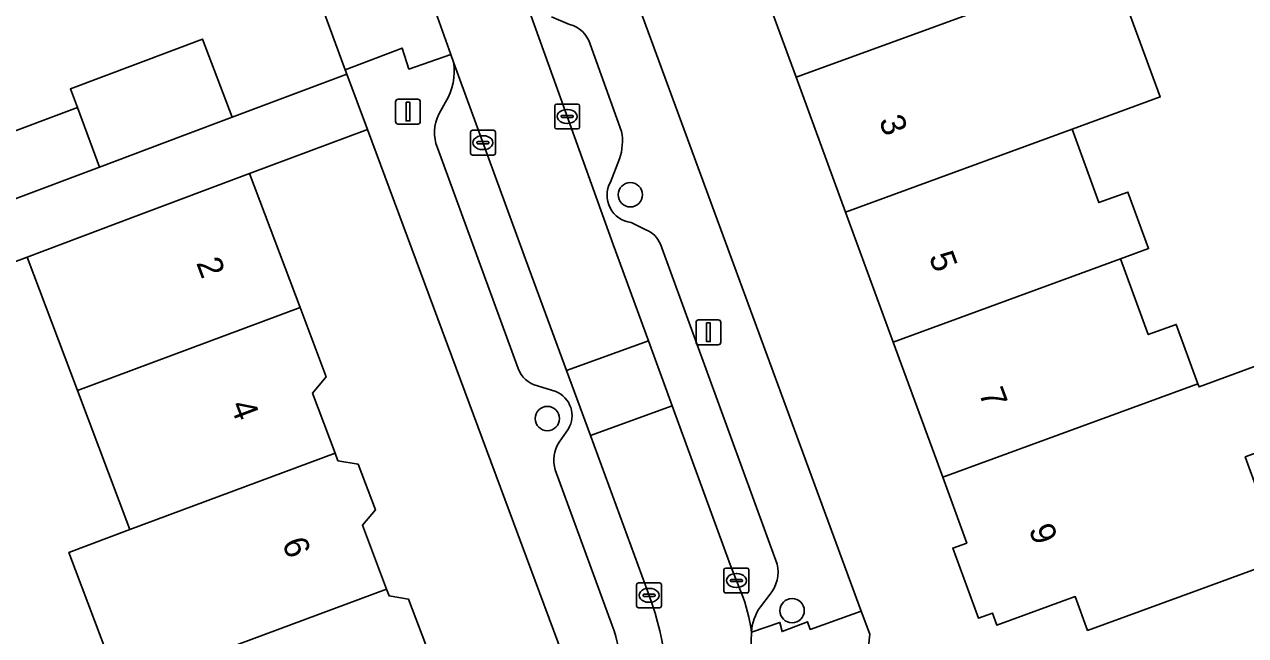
# Model space of a CAD drawing. Extents: x 161258 to 161838, y 380833 to 381727.
# Drawn here: x 161688.41 to 161737.48, y 381440.54 to 381465.11 of the extents above; entities that cross this region are included whole.
import ezdxf

# ---------------------------------------------------------------- set-up
doc = ezdxf.new("R2010")
doc.units = 0
for name, color, linetype in [('IMGEO_Boom', 7, 'Continuous'), ('IMGEO_Erf', 7, 'Continuous'), ('IMGEO_Kolk', 7, 'Continuous'), ('IMGEO_Lichtmast', 7, 'Continuous'), ('IMGEO_Pand', 7, 'Continuous'), ('IMGEO_Pand_nummerreeks', 7, 'Continuous'), ('IMGEO_Parkeervlak_open', 7, 'Continuous'), ('IMGEO_Rijbaan_lokaal_open', 7, 'Continuous'), ('IMGEO_Voetpad_open', 7, 'Continuous')]:
    doc.layers.add(name, color=color, linetype=linetype)

msp = doc.modelspace()

# ---------------------------------------------------------------- linework, layer by layer
at = {"layer": 'IMGEO_Boom'}
for centre in [(161712.757, 381458.263), (161709.426, 381449.266), (161719.258, 381441.543)]:
    msp.add_circle(centre, 0.489, dxfattribs=at)
at = {"layer": 'IMGEO_Erf'}
for points in [[(161650.576, 381442.391), (161665.897, 381448.031), (161665.866, 381448.114), (161663.067, 381447.101), (161662.84, 381447.729), (161661.976, 381450.118), (161664.775, 381451.131), (161665.341, 381449.566), (161680.052, 381455.096), (161679.094, 381457.641), (161682.243, 381458.826), (161683.201, 381456.28), (161687.935, 381458.06), (161687.033, 381460.457), (161690.542, 381461.777), (161690.266, 381462.521), (161695.576, 381464.518), (161696.757, 381461.377), (161701.371, 381463.111), (161701.306, 381463.287), (161700.279, 381466.054), (161692.567, 381486.83), (161622.485, 381460.994)], [(161738.57, 381470.014), (161737.144, 381473.959), (161735.098, 381474.813), (161727.787, 381472.135), (161728.72, 381469.59), (161729.505, 381469.878), (161730.54, 381467.051), (161732.063, 381467.606), (161734.046, 381462.193), (161733.027, 381461.82), (161730.506, 381460.896), (161731.586, 381457.948), (161732.749, 381458.374), (161733.581, 381456.102), (161732.452, 381455.688), (161733.568, 381452.64), (161734.69, 381453.051), (161735.563, 381450.667), (161735.609, 381450.542), (161739.215, 381451.864)], [(161740.346, 381448.778), (161737.465, 381447.722), (161738.967, 381443.62), (161735.595, 381442.384), (161731.131, 381440.748), (161730.632, 381442.111), (161727.489, 381440.959), (161727.31, 381441.447), (161726.747, 381441.241), (161725.715, 381444.058), (161726.278, 381444.264), (161725.309, 381446.909), (161723.319, 381452.34), (161721.406, 381457.561), (161719.415, 381462.994), (161717.453, 381468.348), (161712.809, 381466.642), (161722.039, 381441.525), (161722.379, 381440.599), (161722.102, 381438)], [(161710.363, 381438.89), (161702.199, 381460.88), (161697.459, 381459.12), (161699.487, 381453.726), (161700.532, 381450.947), (161699.991, 381450.289), (161700.897, 381447.88), (161701.013, 381447.57), (161701.823, 381447.436), (161702.514, 381445.6), (161702, 381444.975), (161702.963, 381442.413), (161703.066, 381442.139), (161703.843, 381442.011), (161704.537, 381440.165)], [(161692.261, 381438.418), (161690.203, 381443.888), (161692.652, 381444.802), (161690.549, 381450.391), (161688.53, 381455.758), (161668.011, 381448.039), (161671.253, 381439.144)]]:
    msp.add_lwpolyline(points, dxfattribs=at)
at = {"layer": 'IMGEO_Kolk'}
for p, q in [((161709.721, 381460.985), (161709.721, 381461.837)), ((161709.796, 381461.911), (161710.648, 381461.911)), ((161710.209, 381461.691), (161710.234, 381461.691)), ((161710.722, 381461.837), (161710.722, 381460.985)), ((161709.98, 381461.405), (161709.98, 381461.417)), ((161710.418, 381461.368), (161710.02, 381461.368)), ((161710.023, 381461.454), (161710.421, 381461.454)), ((161710.232, 381461.131), (161710.207, 381461.131)), ((161710.464, 381461.417), (161710.464, 381461.405)), ((161706.337, 381459.931), (161706.337, 381460.783)), ((161706.412, 381460.857), (161707.264, 381460.857)), ((161706.825, 381460.637), (161706.85, 381460.637)), ((161707.338, 381460.783), (161707.338, 381459.931)), ((161710.648, 381460.911), (161709.796, 381460.911)), ((161706.596, 381460.351), (161706.596, 381460.363)), ((161707.034, 381460.314), (161706.636, 381460.314)), ((161706.639, 381460.4), (161707.037, 381460.4)), ((161707.08, 381460.363), (161707.08, 381460.351)), ((161707.264, 381459.857), (161706.412, 381459.857)), ((161706.848, 381460.077), (161706.823, 381460.077)), ((161716.519, 381442.329), (161716.519, 381443.181)), ((161716.594, 381443.255), (161717.446, 381443.255)), ((161717.007, 381443.035), (161717.032, 381443.035)), ((161717.52, 381443.181), (161717.52, 381442.329)), ((161713.011, 381441.735), (161713.011, 381442.587)), ((161713.086, 381442.661), (161713.938, 381442.661)), ((161714.012, 381442.587), (161714.012, 381441.735)), ((161716.778, 381442.749), (161716.778, 381442.761)), ((161717.216, 381442.712), (161716.818, 381442.712)), ((161716.821, 381442.798), (161717.219, 381442.798)), ((161717.03, 381442.475), (161717.005, 381442.475)), ((161717.262, 381442.761), (161717.262, 381442.749)), ((161713.27, 381442.155), (161713.27, 381442.167)), ((161713.708, 381442.118), (161713.31, 381442.118)), ((161713.313, 381442.204), (161713.711, 381442.204)), ((161713.499, 381442.441), (161713.524, 381442.441)), ((161713.754, 381442.167), (161713.754, 381442.155)), ((161717.446, 381442.255), (161716.594, 381442.255)), ((161713.938, 381441.661), (161713.086, 381441.661)), ((161713.522, 381441.881), (161713.497, 381441.881))]:
    msp.add_line(p, q, dxfattribs=at)
for points in [[(161709.721, 381460.985), (161709.721, 381461.837)], [(161709.796, 381461.911), (161710.648, 381461.911)], [(161710.722, 381461.837), (161710.722, 381460.985)], [(161706.337, 381459.931), (161706.337, 381460.783)], [(161706.412, 381460.857), (161707.264, 381460.857)], [(161707.338, 381460.783), (161707.338, 381459.931)], [(161710.648, 381460.911), (161709.796, 381460.911)], [(161707.264, 381459.857), (161706.412, 381459.857)], [(161716.519, 381442.329), (161716.519, 381443.181)], [(161716.594, 381443.255), (161717.446, 381443.255)], [(161717.52, 381443.181), (161717.52, 381442.329)], [(161713.011, 381441.735), (161713.011, 381442.587)], [(161713.086, 381442.661), (161713.938, 381442.661)], [(161714.012, 381442.587), (161714.012, 381441.735)], [(161717.446, 381442.255), (161716.594, 381442.255)], [(161713.938, 381441.661), (161713.086, 381441.661)]]:
    msp.add_lwpolyline(points, dxfattribs=at)
for centre, radius, start, end in [((161709.798, 381461.835), 0.0765, 91.552, 178.448), ((161709.798, 381461.835), 0.0765, 91.552, 178.448), ((161710.646, 381461.835), 0.0765, 1.552, 88.448), ((161710.646, 381461.835), 0.0765, 1.552, 88.448), ((161710.02, 381461.414), 0.0403, 85.8775, 175.7526), ((161710.017, 381461.404), 0.0366, 178.938, 274.7102), ((161710.421, 381461.411), 0.043, 264.8664, 352.4533), ((161710.425, 381461.416), 0.0386, 1.7309, 96.639), ((161706.414, 381460.781), 0.0765, 91.552, 178.448), ((161706.414, 381460.781), 0.0765, 91.552, 178.448), ((161707.262, 381460.781), 0.0765, 1.552, 88.448), ((161707.262, 381460.781), 0.0765, 1.552, 88.448), ((161709.798, 381460.987), 0.0765, 181.552, 268.448), ((161709.798, 381460.987), 0.0765, 181.552, 268.448), ((161710.646, 381460.987), 0.0765, 271.552, 358.448), ((161710.646, 381460.987), 0.0765, 271.552, 358.448), ((161706.636, 381460.36), 0.0403, 85.8775, 175.7526), ((161706.633, 381460.35), 0.0366, 178.938, 274.7102), ((161707.037, 381460.357), 0.043, 264.8664, 352.4533), ((161707.041, 381460.362), 0.0386, 1.7309, 96.639), ((161706.414, 381459.933), 0.0765, 181.552, 268.448), ((161706.414, 381459.933), 0.0765, 181.552, 268.448), ((161707.262, 381459.933), 0.0765, 271.552, 358.448), ((161707.262, 381459.933), 0.0765, 271.552, 358.448), ((161716.596, 381443.179), 0.0765, 91.552, 178.448), ((161716.596, 381443.179), 0.0765, 91.552, 178.448), ((161717.444, 381443.179), 0.0765, 1.552, 88.448), ((161717.444, 381443.179), 0.0765, 1.552, 88.448), ((161713.088, 381442.585), 0.0765, 91.552, 178.448), ((161713.088, 381442.585), 0.0765, 91.552, 178.448), ((161713.936, 381442.585), 0.0765, 1.552, 88.448), ((161713.936, 381442.585), 0.0765, 1.552, 88.448), ((161716.818, 381442.758), 0.0403, 85.8775, 175.7526), ((161716.815, 381442.748), 0.0366, 178.938, 274.7102), ((161717.219, 381442.755), 0.043, 264.8664, 352.4533), ((161717.223, 381442.76), 0.0386, 1.7309, 96.639), ((161713.31, 381442.164), 0.0403, 85.8775, 175.7526), ((161713.307, 381442.154), 0.0366, 178.938, 274.7102), ((161713.711, 381442.161), 0.043, 264.8664, 352.4533), ((161713.715, 381442.166), 0.0386, 1.7309, 96.639), ((161716.596, 381442.331), 0.0765, 181.552, 268.448), ((161716.596, 381442.331), 0.0765, 181.552, 268.448), ((161717.444, 381442.331), 0.0765, 271.552, 358.448), ((161717.444, 381442.331), 0.0765, 271.552, 358.448), ((161713.088, 381441.737), 0.0765, 181.552, 268.448), ((161713.088, 381441.737), 0.0765, 181.552, 268.448), ((161713.936, 381441.737), 0.0765, 271.552, 358.448), ((161713.936, 381441.737), 0.0765, 271.552, 358.448)]:
    msp.add_arc(centre, radius, start, end, dxfattribs=at)
for centre, major_axis, ratio, start_param, end_param in [((161710.208, 381461.411), (-0.387, 0.002), 0.722429, 4.712389, 7.853982), ((161710.233, 381461.411), (-0.39, 0.002), 0.717154, 1.570796, 4.712389), ((161706.824, 381460.357), (-0.387, 0.002), 0.722429, 4.712389, 7.853982), ((161706.849, 381460.357), (-0.39, 0.002), 0.717154, 1.570796, 4.712389), ((161717.006, 381442.755), (-0.387, 0.002), 0.722429, 4.712389, 7.853982), ((161717.031, 381442.755), (-0.39, 0.002), 0.717154, 1.570796, 4.712389), ((161713.498, 381442.161), (-0.387, 0.002), 0.722429, 4.712389, 7.853982), ((161713.523, 381442.161), (-0.39, 0.002), 0.717154, 1.570796, 4.712389)]:
    msp.add_ellipse(centre, major_axis=major_axis, ratio=ratio, start_param=start_param, end_param=end_param, dxfattribs=at)
at = {"layer": 'IMGEO_Lichtmast'}
for p, q in [((161703.43, 381462.105), (161704.22, 381462.105)), ((161704.22, 381462.105), (161703.43, 381462.105)), ((161703.33, 381461.205), (161703.33, 381462.005)), ((161703.33, 381462.005), (161703.33, 381461.205)), ((161704.32, 381462.005), (161704.32, 381461.205)), ((161704.32, 381461.205), (161704.32, 381462.005)), ((161704.22, 381461.105), (161703.43, 381461.105)), ((161703.43, 381461.105), (161704.22, 381461.105)), ((161715.402, 381452.334), (161715.402, 381453.134)), ((161715.402, 381453.134), (161715.402, 381452.334)), ((161715.502, 381453.234), (161716.292, 381453.234)), ((161716.292, 381453.234), (161715.502, 381453.234)), ((161716.392, 381453.134), (161716.392, 381452.334)), ((161716.392, 381452.334), (161716.392, 381453.134)), ((161716.292, 381452.234), (161715.502, 381452.234)), ((161715.502, 381452.234), (161716.292, 381452.234))]:
    msp.add_line(p, q, dxfattribs=at)
for points in [[(161703.75, 381461.98), (161703.9, 381461.98), (161703.9, 381461.23), (161703.75, 381461.23), (161703.75, 381461.98)], [(161715.822, 381453.109), (161715.972, 381453.109), (161715.972, 381452.359), (161715.822, 381452.359), (161715.822, 381453.109)]]:
    msp.add_lwpolyline(points, dxfattribs=at)
for centre, start, end in [((161703.43, 381462.005), 90, 180), ((161703.43, 381462.005), 90, 180), ((161704.22, 381462.005), 0, 90), ((161704.22, 381462.005), 360, 90), ((161703.43, 381461.205), 180, 270), ((161703.43, 381461.205), 180, 270), ((161704.22, 381461.205), 270, 0), ((161704.22, 381461.205), 270, 0), ((161715.502, 381453.134), 90, 180), ((161715.502, 381453.134), 90, 180), ((161716.292, 381453.134), 0, 90), ((161716.292, 381453.134), 360, 90), ((161715.502, 381452.334), 180, 270), ((161715.502, 381452.334), 180, 270), ((161716.292, 381452.334), 270, 0), ((161716.292, 381452.334), 270, 0)]:
    msp.add_arc(centre, 0.1, start, end, dxfattribs=at)
at = {"layer": 'IMGEO_Pand'}
for points in [[(161728.72, 381469.59), (161727.787, 381472.135), (161722.096, 381470.05), (161717.453, 381468.348), (161719.415, 381462.994), (161730.54, 381467.051), (161729.505, 381469.878)], [(161730.54, 381467.051), (161719.415, 381462.994), (161721.406, 381457.561), (161730.506, 381460.896), (161733.027, 381461.82), (161734.046, 381462.193), (161732.063, 381467.606)], [(161690.266, 381462.521), (161690.542, 381461.777), (161691.433, 381459.375), (161694.766, 381460.628), (161696.757, 381461.377), (161695.576, 381464.518)], [(161691.433, 381459.375), (161690.542, 381461.777), (161687.033, 381460.457), (161687.935, 381458.06)], [(161732.749, 381458.374), (161731.586, 381457.948), (161730.506, 381460.896), (161721.406, 381457.561), (161723.319, 381452.34), (161732.452, 381455.688), (161733.581, 381456.102)], [(161690.549, 381450.391), (161699.487, 381453.726), (161697.459, 381459.12), (161692.779, 381457.36), (161688.53, 381455.758)], [(161734.69, 381453.051), (161733.568, 381452.64), (161732.452, 381455.688), (161723.319, 381452.34), (161725.309, 381446.909), (161735.563, 381450.667)], [(161700.897, 381447.88), (161699.991, 381450.289), (161700.532, 381450.947), (161699.487, 381453.726), (161690.549, 381450.391), (161692.652, 381444.802)], [(161735.563, 381450.667), (161725.309, 381446.909), (161726.278, 381444.264), (161725.715, 381444.058), (161726.747, 381441.241), (161727.31, 381441.447), (161727.489, 381440.959), (161730.632, 381442.111), (161731.131, 381440.748), (161735.595, 381442.384), (161738.967, 381443.62), (161737.465, 381447.722), (161740.346, 381448.778), (161739.215, 381451.864), (161735.609, 381450.542)], [(161702, 381444.975), (161702.514, 381445.6), (161701.823, 381447.436), (161701.013, 381447.57), (161700.897, 381447.88), (161692.652, 381444.802), (161690.203, 381443.888), (161692.261, 381438.418), (161693.067, 381438.719), (161693.35, 381438.825), (161693.713, 381438.96), (161702.963, 381442.413)], [(161703.945, 381433.024), (161703.968, 381433.23), (161704.731, 381433.565), (161704.948, 381435.524), (161704.273, 381436.021), (161704.518, 381438.234), (161704.027, 381439.544), (161704.537, 381440.165), (161703.843, 381442.011), (161703.066, 381442.139), (161702.963, 381442.413), (161693.713, 381438.96), (161694.64, 381436.494), (161694.374, 381434.1)]]:
    msp.add_lwpolyline(points, close=True, dxfattribs=at)
at = {"layer": 'IMGEO_Parkeervlak_open'}
for points in [[(161708.399, 381466.5), (161712.064, 381456.269), (161713.482, 381452.388), (161714.435, 381449.777), (161716.781, 381443.354), (161717.213, 381442.272)], [(161710.318, 381465.111), (161709.596, 381465.418)], [(161712.409, 381460.812), (161711.14, 381464.321)], [(161713.514, 381442.157), (161711.153, 381448.587), (161710.194, 381451.196), (161708.698, 381455.271), (161705.655, 381463.593)], [(161705.335, 381461.985), (161705.066, 381461.501)], [(161705.006, 381460.153), (161708.247, 381451.281)], [(161711.956, 381458.77), (161712.328, 381459.708)], [(161713.383, 381456.848), (161712.788, 381457.142)], [(161718.663, 381443.411), (161713.965, 381456.275)], [(161709.031, 381450.58), (161709.766, 381450.348)], [(161710.268, 381448.849), (161709.898, 381448.317)], [(161709.742, 381447.2), (161712.028, 381440.946)], [(161717.983, 381441.7), (161718.379, 381442.206)]]:
    msp.add_lwpolyline(points, dxfattribs=at)
for centre, radius, start, end in [((161710.015, 381463.973), 1.178, 17.197, 75.0775), ((161703.29, 381463.228), 2.393, 328.7116, 8.7782), ((161706.552, 381460.76), 1.661, 153.4836, 201.4192), ((161710.145, 381460.423), 2.297, 341.8597, 9.7478), ((161712.936, 381458.244), 1.112, 151.8068, 262.3324), ((161713.057, 381455.935), 0.97, 20.5457, 70.3472), ((161709.309, 381451.68), 1.134, 200.5785, 255.8196), ((161709.375, 381449.384), 1.041, 329.0827, 67.9477), ((161711.015, 381447.592), 1.332, 147.0087, 197.0903), ((161717.223, 381443.114), 1.47, 321.8356, 11.641), ((161701.665, 381437.812), 12.62, 353.0554, 20.1388), ((161711.529, 381439.963), 6.135, 6.7092, 22.1073), ((161719.588, 381440.558), 1.97, 144.5699, 176.4501), ((161704.815, 381438.358), 7.663, 352.1728, 19.7417)]:
    msp.add_arc(centre, radius, start, end, dxfattribs=at)
at = {"layer": 'IMGEO_Rijbaan_lokaal_open'}
for points in [[(161696.56, 381488.313), (161696.636, 381488.131), (161698.582, 381482.625), (161703.946, 381468.421), (161705.542, 381463.901), (161705.655, 381463.593), (161708.698, 381455.271), (161710.194, 381451.196), (161713.482, 381452.388), (161712.064, 381456.269), (161708.399, 381466.5), (161708.292, 381466.799), (161707.19, 381469.886), (161707.125, 381470.068), (161707.048, 381470.326), (161703.495, 381479.945), (161699.851, 381489.581)], [(161717.213, 381442.272), (161716.781, 381443.354), (161714.435, 381449.777), (161711.153, 381448.587), (161713.514, 381442.157)], [(161714.193, 381436.286), (161712.841, 381424.462), (161709.639, 381395.601), (161712.933, 381395.246), (161713.952, 381404.688), (161715.817, 381421.255), (161717.229, 381433.087), (161717.434, 381435.638), (161717.456, 381435.916), (161717.622, 381440.68)]]:
    msp.add_lwpolyline(points, dxfattribs=at)
msp.add_lwpolyline([(161714.435, 381449.777), (161713.482, 381452.388), (161710.194, 381451.196), (161711.153, 381448.587)], close=True, dxfattribs=at)
for centre, radius, start, end in [((161701.665, 381437.812), 12.62, 353.0554, 20.1388), ((161711.529, 381439.963), 6.135, 6.7092, 22.1073)]:
    msp.add_arc(centre, radius, start, end, dxfattribs=at)
at = {"layer": 'IMGEO_Voetpad_open'}
for points in [[(161703.946, 381468.421), (161702.217, 381467.754), (161702.57, 381466.902), (161700.279, 381466.054), (161701.306, 381463.287), (161703.587, 381464.157), (161703.863, 381463.318), (161705.542, 381463.901)], [(161722.379, 381440.599), (161722.039, 381441.525), (161719.985, 381440.791), (161719.872, 381441.096), (161718.855, 381440.706), (161718.768, 381441.075), (161717.622, 381440.68), (161717.456, 381435.916), (161719.712, 381435.676), (161720.083, 381436.551), (161721.934, 381436.431), (161722.102, 381438)]]:
    msp.add_lwpolyline(points, close=True, dxfattribs=at)
for points in [[(161717.622, 381440.68), (161718.768, 381441.075), (161718.855, 381440.706), (161719.872, 381441.096), (161719.985, 381440.791), (161722.039, 381441.525), (161712.809, 381466.642)], [(161709.596, 381465.418), (161710.318, 381465.111)], [(161705.655, 381463.593), (161705.542, 381463.901), (161703.863, 381463.318), (161703.587, 381464.157), (161701.306, 381463.287), (161701.371, 381463.111), (161702.199, 381460.88), (161710.363, 381438.89), (161703.682, 381379.623), (161705.838, 381379.36), (161705.904, 381379.957), (161707.873, 381379.766)], [(161711.14, 381464.321), (161712.409, 381460.812)], [(161671.253, 381439.144), (161668.011, 381448.039), (161688.53, 381455.758), (161692.779, 381457.36), (161697.459, 381459.12), (161702.199, 381460.88), (161701.371, 381463.111), (161696.757, 381461.377), (161694.766, 381460.628), (161691.433, 381459.375), (161687.935, 381458.06), (161683.201, 381456.28), (161680.052, 381455.096), (161665.341, 381449.566), (161665.866, 381448.114), (161665.897, 381448.031), (161650.576, 381442.391)], [(161705.066, 381461.501), (161705.335, 381461.985)], [(161708.247, 381451.281), (161705.006, 381460.153)], [(161712.328, 381459.708), (161711.956, 381458.77)], [(161712.788, 381457.142), (161713.383, 381456.848)], [(161713.965, 381456.275), (161718.663, 381443.411)], [(161709.766, 381450.348), (161709.031, 381450.58)], [(161709.898, 381448.317), (161710.268, 381448.849)], [(161712.028, 381440.946), (161709.742, 381447.2)], [(161718.379, 381442.206), (161717.983, 381441.7)]]:
    msp.add_lwpolyline(points, dxfattribs=at)
for centre, radius, start, end in [((161710.015, 381463.973), 1.178, 17.197, 75.0775), ((161703.29, 381463.228), 2.393, 328.7116, 8.7782), ((161706.552, 381460.76), 1.661, 153.4836, 201.4192), ((161710.145, 381460.423), 2.297, 341.8597, 9.7478), ((161712.936, 381458.244), 1.112, 151.8068, 262.3324), ((161713.057, 381455.935), 0.97, 20.5457, 70.3472), ((161709.309, 381451.68), 1.134, 200.5785, 255.8196), ((161709.375, 381449.384), 1.041, 329.0827, 67.9477), ((161711.015, 381447.592), 1.332, 147.0087, 197.0903), ((161717.223, 381443.114), 1.47, 321.8356, 11.641), ((161719.588, 381440.558), 1.97, 144.5699, 176.4501), ((161704.815, 381438.358), 7.663, 352.1728, 19.7417)]:
    msp.add_arc(centre, radius, start, end, dxfattribs=at)

# ---------------------------------------------------------------- texts
at = {"layer": 'IMGEO_Pand_nummerreeks'}
for s, rotation, p in [('3', 290.1221, (161722.736, 381461.257)), ('2', 290.606, (161695.306, 381455.529)), ('5', 290.1221, (161724.743, 381455.779)), ('7', 290.1221, (161726.75, 381450.301)), ('4', 290.6527, (161696.671, 381449.806)), ('9', 290.1241, (161728.757, 381444.824)), ('6', 290.6549, (161698.755, 381444.278))]:
    msp.add_text(s, height=1, rotation=rotation, dxfattribs=at).set_placement(p)

doc.saveas('drawing.dxf')
